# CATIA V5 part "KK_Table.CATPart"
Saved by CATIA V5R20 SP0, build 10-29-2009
Part number: Table
Bounding box of the stored display mesh (mm): x -98.603 to 98.603, y -75 to 168.333, z 72.5 to 122.5
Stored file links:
  G:\Khaled_CFAO_2011\ST2M\ST2M_GR1\msallin\Khaled\Version_Finale\KK_Table.CATPart
  C:\Users\Mathieu\Desktop\Think Motion\JOUG-MELEE2.CATProduct
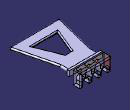
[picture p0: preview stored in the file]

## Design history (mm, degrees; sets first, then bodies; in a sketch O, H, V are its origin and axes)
External parameters (linked from other documents)
  `External.Taille du joug` = 100 mm
Set1
  Plane1: linked copy from another document
  Line1: linked copy from another document
  Point1 to Point3: linked copy from another document
  Plane2: linked copy from another document
  Point4: linked copy from another document
  Line2 to Line4: linked copy from another document
Set2
  Plane3: type Offset, RefPlane Plane1, Offset 12.5 {= `External.Taille du joug` /8}
  Plane4: type Normal, Curve Line4
Body1 (main body)
  Sketch1 on Plane3, origin (0, 0, 112.5), H (1, 0, 0), V (0, 1, 0)
    line L1 (-60, 120) -> (60, 120)
    line L2 (60, 120) -> (60, 86.6667)
    point P4 (100, -75)
    line L3 (100, -75) -> (-100, -75)
    line L4 (-100, -75) -> (-60, 86.6667)
    line L5 (-60, 86.6667) -> (-60, 120)
    line L6 (100, -75) -> (60, 86.6667)
    length L1 = 120 {= `External.Taille du joug` *6/5}
    distance L2 V = 60 {= Sketch1.length(L1) /2}
    length L2 = 33.3333 {= `External.Taille du joug` /3}
    length L5 = 33.3333 {= Sketch1.length(L2)}
    distance H L1 = 120 {= Sketch1.length(L1)}
    length L3 = 200 {= 2*`External.Taille du joug`}
    distance P4 V = 100 {= Sketch1.length(L3) /2}
    distance L3 H = 75 {= `External.Taille du joug` *3/4}
    horizontal: L1 H, L3 H
    vertical: L2 V, L5 V
  Sketch2 on Plane2, origin (-0.277, 81.5078, 20.3771), H (-1, -0.0034, 0), V (0.0008, -0.2425, 0.9701)
    arc A1 centre (19.7906, 82.0734) radius 5 from (24.4728, 80.3195) to (18.3843, 86.8716) ccw
    reference projected point E1 (19.7906, 82.0734) from Point4
    point P2 (24.4728, 80.3195)
    point P3 (18.3843, 86.8716)
    reference projected line E2 (19.7906, 82.0734) -> (50, -21.0042) from Line2
    reference projected line E3 (19.7906, 82.0734) -> (50, -21.0042) from Line2
    line L1 (18.3843, 86.8716) -> (17.8218, 88.7909)
    line L2 (17.8218, 88.7909) -> (27.8218, 88.7909)
    line L3 (27.8218, 88.7909) -> (27.8218, 82.1242)
    line L4 (27.8218, 82.1242) -> (24.4728, 80.3195)
    radius A1 = 5 {= `External.Taille du joug` /20}
    distance P3 E2 = 0
    distance P2 E3 = 4 {= `External.Taille du joug` /25}
    length L1 = 2 {= `External.Taille du joug` /50}
    length L2 = 10 {= `External.Taille du joug` /10}
    length L3 = 6.6667 {= `External.Taille du joug` /15}
    concentricity: E1 A1
    coincidence: L1 E1
    vertical: L3 V
    horizontal: L2 H
  Shaft1: profile Sketch2, axis Line2, angle 360
  CircPattern1: of Shaft1, instances 3, angular step 120, axis from xy-plane
  Mirror1: of the body so far, about Plane4
  Pad1: profile Sketch1, direction (0, 0, -1), length 10 {= `External.Taille du joug` /10}
  Sketch3 on start face of Pad1, origin (0, 0, 112.5), H (1, 0, 0), V (0, 1, 0)
    line L1 (-50, -33.3333) -> (50, -33.3333)
    point P2 (50, -33.3333)
    line L2 (50, -33.3333) -> (12.5, 59.3691)
    point P3 (12.5, 59.3691)
    line L3 (12.5, 59.3691) -> (-12.5, 59.3691)
    line L4 (-12.5, 59.3691) -> (-50, -33.3333)
    length L1 = 100 {= `External.Taille du joug`}
    distance P2 V = 50 {= Sketch3.length(L1) /2}
    length L3 = 25 {= `External.Taille du joug` /4}
    distance P3 V = 12.5 {= Sketch3.length(L3) /2}
    length L2 = 100 {= `External.Taille du joug`}
    distance L1 H = 33.3333 {= `External.Taille du joug` /3}
    horizontal: L1 H, L3 H
  Pocket1: profile Sketch3, direction (0, 0, -1), length 10 {= Pad1.FirstLimit.Length}
  Fillet1: radius 5, on edge [end face of Pad1 | face of Pad1 from Sketch1.L2]; edge [face of Pad1 from Sketch1.L2 | start face of Pad1]; edge [end face of Pad1 | face of Pad1 from Sketch1.L6]; edge [face of Pad1 from Sketch1.L6 | start face of Pad1]; edge [face of Pad1 from Sketch1.L3 | face of Pad1 from Sketch1.L6]; face of Pad1 from Sketch1.L3; edge [end face of Pad1 | face of Pad1 from Sketch1.L4]; edge [face of Pad1 from Sketch1.L4 | start face of Pad1]; edge [end face of Pad1 | face of Pad1 from Sketch1.L5]; edge [face of Pad1 from Sketch1.L5 | start face of Pad1]
  Fillet2: radius 4, on edge [start face of Pad1 | face of Pocket1 from Sketch3.L1]; edge [start face of Pad1 | face of Pocket1 from Sketch3.L4]; edge [start face of Pad1 | face of Pocket1 from Sketch3.L3]; edge [start face of Pad1 | face of Pocket1 from Sketch3.L2]; edge [face of Pocket1 from Sketch3.L3 | end face of Pad1]; edge [face of Pocket1 from Sketch3.L4 | end face of Pad1]; edge [face of Pocket1 from Sketch3.L1 | end face of Pad1]; edge [face of Pocket1 from Sketch3.L2 | end face of Pad1]
  Sketch4 on face of Pad1 from Sketch1.L1, origin (0, 120, 0), H (-1, 0, 0), V (0, 0, 1)
    line L1 (-65, 117.5) -> (65, 117.5)
    line L2 (65, 117.5) -> (65, 97.5)
    line L3 (65, 97.5) -> (-65, 97.5)
    line L4 (-65, 97.5) -> (-65, 117.5)
    reference projected line E1 (-60, 112.5) -> (60, 112.5) from edge [face of Pad1 from Sketch1.L1 | start face of Pad1]
    reference projected line E2 (-60, 102.5) -> (60, 102.5) from edge [end face of Pad1 | face of Pad1 from Sketch1.L1]
    reference projected point E3 (60, 107.5) from vertex [face of Pad1 from Sketch1.L1 | face of Fillet1 | face of Fillet1]
    reference projected point E4 (-60, 107.5) from vertex [face of Fillet1 | face of Pad1 from Sketch1.L1]
    distance E1 L1 = 5 {= `External.Taille du joug` /20}
    distance L3 E2 = 5 {= Sketch4.distance(E1 L1)}
    distance E3 L2 = 5 {= Sketch4.distance(E1 L1)}
    distance E4 L4 = 5 {= Sketch4.distance(E3 L2)}
    horizontal: L1 H, L3 H
    vertical: L2 V, L4 V
  Pad2: profile Sketch4, direction (0, 1, 0), length 8.3333 {= `External.Taille du joug` /12}
  Sketch5 on end face of Pad2, origin (0, 128.3333, 0), H (-1, 0, 0), V (0, 0, 1)
    circle A1 centre (32.5, 107.5) radius 5
    point P1 (32.5, 107.5)
    circle A2 centre (0, 107.5) radius 5
    point P2 (0, 107.5)
    circle A3 centre (-32.5, 107.5) radius 5
    point P3 (-32.5, 107.5)
    reference projected line E1 (65, 117.5) -> (-65, 117.5) from edge [face of Pad2 from Sketch4.L1 | end face of Pad2]
    reference projected line E2 (65, 117.5) -> (-65, 117.5) from edge [face of Pad2 from Sketch4.L1 | end face of Pad2]
    reference projected line E3 (65, 117.5) -> (-65, 117.5) from edge [face of Pad2 from Sketch4.L1 | end face of Pad2]
    reference projected line E4 (65, 97.5) -> (65, 117.5) from edge [face of Pad2 from Sketch4.L2 | end face of Pad2]
    distance P1 E1 = 10 {= `External.Taille du joug` /10}
    distance P2 E2 = 10 {= Sketch5.distance(P1 E1)}
    distance P3 E3 = 10 {= Sketch5.distance(P2 E2)}
    radius A1 = 5 {= `External.Taille du joug` /20}
    radius A2 = 5 {= Sketch5.radius(A1)}
    radius A3 = 5 {= Sketch5.radius(A2)}
    distance E4 P1 = 32.5 {= `External.Taille du joug` *(6/5+2/20)/4}
    distance P2 P1 = 32.5 {= Sketch5.distance(E4 P1)}
    distance P3 P2 = 32.5 {= Sketch5.distance(P2 P1)}
  Pad3: profile Sketch5, direction (0, 1, 0), length 10 {= `External.Taille du joug` /10}
  Sketch6 on end face of Pad3, origin (0, 138.3333, 0), H (-1, 0, 0), V (0, 0, 1)
    line L1 (-60, 122.5) -> (60, 122.5)
    line L2 (60, 122.5) -> (60, 72.5)
    line L3 (60, 72.5) -> (48, 72.5)
    line L4 (48, 72.5) -> (48, 85)
    line L5 (-60, 122.5) -> (-60, 72.5)
    point P6 (-60, 72.5)
    line L6 (-60, 72.5) -> (-48, 72.5)
    line L7 (-48, 72.5) -> (-48, 85)
    line L8 (-24, 85) -> (-24, 72.5)
    point P10 (-24, 72.5)
    line L9 (-24, 72.5) -> (-12, 72.5)
    line L10 (-12, 72.5) -> (-12, 85)
    line L11 (12, 85) -> (12, 72.5)
    point P14 (12, 72.5)
    line L12 (12, 72.5) -> (24, 72.5)
    line L13 (24, 72.5) -> (24, 85)
    arc A1 centre (-36, 85) radius 12 from (-48, 85) to (-24, 85) cw
    arc A2 centre (0, 85) radius 12 from (-12, 85) to (12, 85) cw
    arc A3 centre (36, 85) radius 12 from (24, 85) to (48, 85) cw
    reference projected line E1 (-65, 117.5) -> (-65, 97.5) from edge [face of Pad2 from Sketch4.L4 | end face of Pad2]
    reference projected line E2 (65, 117.5) -> (-65, 117.5) from edge [face of Pad2 from Sketch4.L1 | end face of Pad2]
    length L1 = 120 {= `External.Taille du joug` *6/5}
    distance L5 E1 = 5 {= `External.Taille du joug` /20}
    length L6 = 12 {= Sketch6.length(L1) /10}
    length L9 = 12 {= Sketch6.length(L6)}
    length L12 = 12 {= Sketch6.length(L9)}
    length L3 = 12 {= Sketch6.length(L12)}
    radius A3 = 12 {= Sketch6.length(L12)}
    radius A2 = 12 {= Sketch6.radius(A3)}
    radius A1 = 12 {= Sketch6.radius(A2)}
    length L2 = 50 {= `External.Taille du joug` /2}
    length L4 = 12.5 {= Sketch6.length(L2) /4}
    length L11 = 12.5 {= Sketch6.length(L4)}
    length L8 = 12.5 {= Sketch6.length(L4)}
    distance L1 E2 = 5 {= `External.Taille du joug` /20}
    horizontal: L1 H, L3 H, L6 H, L9 H, L12 H
    vertical: L2 V, L4 V, L5 V, L7 V, L8 V, L10 V, L11 V, L13 V
    coincidence: P6 L3, P10 L3, P14 L3
    tangency: A1 L8, A2 L11, A3 L4
  Pad4: profile Sketch6, direction (0, 1, 0), length 30 {= `External.Taille du joug` *3/10}
  Fillet3: radius 5, on end face of Pad4
  Sketch7 on face of Pad1 from Sketch1.L1, origin (0, 120, 232.5), H (1, 0, 0), V (0, 0, -1)
    line L1 (-60, 120) -> (60, 120)
    line L2 (60, 120) -> (60, 86.6667)
    point P4 (100, -75)
    line L3 (100, -75) -> (-100, -75)
    line L4 (-100, -75) -> (-60, 86.6667)
    line L5 (-60, 86.6667) -> (-60, 120)
    line L6 (100, -75) -> (60, 86.6667)
    length L1 = 120 {= `External.Taille du joug` *6/5}
    distance L2 V = 60 {= Sketch7.length(L1) /2}
    length L2 = 33.3333 {= `External.Taille du joug` /3}
    length L5 = 33.3333 {= Sketch7.length(L2)}
    distance H L1 = 120 {= Sketch7.length(L1)}
    length L3 = 200 {= 2*`External.Taille du joug`}
    distance P4 V = 100 {= Sketch7.length(L3) /2}
    distance L3 H = 75 {= `External.Taille du joug` *3/4}
    horizontal: L1 H, L3 H
    vertical: L2 V, L5 V
  Pad5: profile Sketch7, direction (0, -1, 0), length 10 {= `External.Taille du joug` /10}
Current feature: Fillet3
